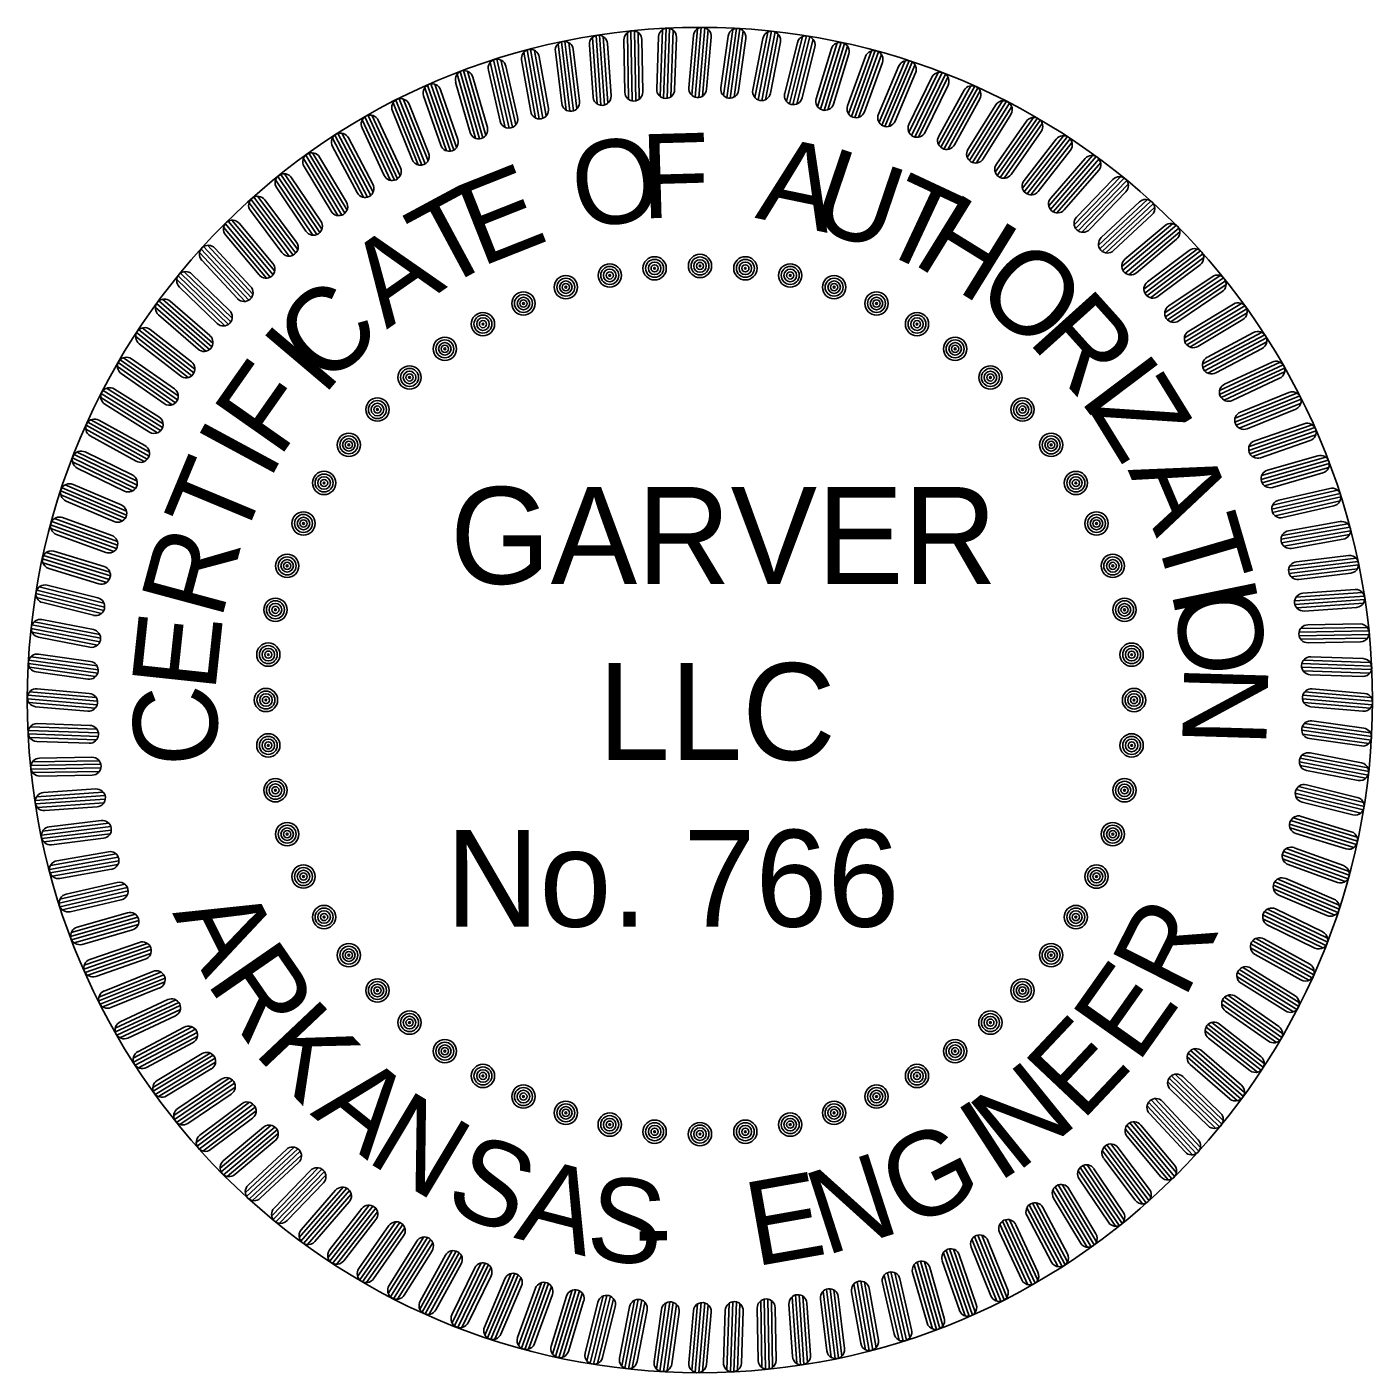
# Model space of a CAD drawing. Extents: x 0 to 19, y -0.6 to 11.2.
# Drawn here: x 17.822 to 19.023, y 2.492 to 3.693 of the extents above; entities that cross this region are included whole.
import ezdxf

# ---------------------------------------------------------------- set-up
doc = ezdxf.new("R2010")
doc.units = 0
for name, color, linetype in [('G-ANNO-STMP', 7, 'Continuous'), ('G-ANNO-TEXT', 7, 'Continuous'), ('G-No Plot-Stamp-1', 7, 'Continuous')]:
    doc.layers.add(name, color=color, linetype=linetype)

# ---------------------------------------------------------------- blocks, each defined once
blk = doc.blocks.new('SEALDO')
at = {"layer": 'G-ANNO-TEXT'}
for radius in [0.0396, 0.0305, 0.0213, 0.0122, 0.00305]:
    blk.add_circle((1.403, -0.4559), radius, dxfattribs=at)
blk = doc.blocks.new('SEALRI')
at = {"layer": 'G-ANNO-TEXT'}
for p, q in [((-0.0226, 2.2583), (-0.0381, 2.0809)), ((-0.0083, 2.2815), (-0.0281, 2.0555)), ((0.0043, 2.2859), (-0.0164, 2.049)), ((0.0164, 2.2848), (-0.0043, 2.0479)), ((0.0281, 2.2783), (0.0083, 2.0523)), ((0.0226, 2.0756), (0.0381, 2.253))]:
    blk.add_line(p, q, dxfattribs=at)
for centre, start, end in [((0.0078, 2.2556), 355, 175), ((-0.0078, 2.0782), 175, 355)]:
    blk.add_arc(centre, 0.0305, start, end, dxfattribs=at)

msp = doc.modelspace()

# ---------------------------------------------------------------- linework, layer by layer
at = {"layer": 'G-No Plot-Stamp-1'}
msp.add_circle((18.4222, 3.0925), 0.6, dxfattribs=at)

# ---------------------------------------------------------------- block references
at = {"layer": 'G-ANNO-STMP'}
for name, xscale, yscale, rotation in [('SEALRI', 0.2624620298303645, 0.2624620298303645, 9), ('SEALRI', 0.2624620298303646, 0.26246202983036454, 6), ('SEALRI', 0.2624620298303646, 0.2624620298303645, 3.0000000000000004), ('SEALRI', 0.26246202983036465, 0.2624620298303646, -2.9999999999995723), ('SEALRI', 0.2624620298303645, 0.2624620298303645, -5.9999999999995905), ('SEALRI', 0.2624620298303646, 0.26246202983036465, -8.999999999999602), ('SEALRI', 0.2624620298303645, 0.2624620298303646, 15.000000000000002), ('SEALRI', 0.2624620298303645, 0.2624620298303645, 12.000000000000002), ('SEALRI', 0.2624620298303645, 0.26246202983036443, -11.999999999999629), ('SEALRI', 0.2624620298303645, 0.2624620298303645, -14.999999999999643), ('SEALRI', 0.2624620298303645, 0.26246202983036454, 18), ('SEALRI', 0.26246202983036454, 0.2624620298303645, -17.99999999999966), ('SEALRI', 0.26246202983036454, 0.26246202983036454, 20.999999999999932), ('SEALRI', 0.2624620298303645, 0.26246202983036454, -20.999999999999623), ('SEALRI', 0.26246202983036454, 0.26246202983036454, 23.99999999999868), ('SEALRI', 0.2624620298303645, 0.26246202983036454, -23.999999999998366), ('SEALRI', 0.2624620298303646, 0.26246202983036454, 26.99999999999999), ('SEALRI', 0.26246202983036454, 0.26246202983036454, -26.999999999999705), ('SEALRI', 0.2624620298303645, 0.2624620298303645, 30.00000000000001), ('SEALRI', 0.26246202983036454, 0.2624620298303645, -29.99999999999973), ('SEALRI', 0.2624620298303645, 0.26246202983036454, 33), ('SEALRI', 0.26246202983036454, 0.2624620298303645, -32.999999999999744), ('SEALRI', 0.2624620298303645, 0.2624620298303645, 36), ('SEALRI', 0.2624620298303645, 0.2624620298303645, -35.999999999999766), ('SEALRI', 0.26246202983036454, 0.26246202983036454, 38.999999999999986), ('SEALRI', 0.26246202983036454, 0.2624620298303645, -38.999999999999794), ('SEALRI', 0.26246202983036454, 0.2624620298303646, 41.999999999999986), ('SEALRI', 0.26246202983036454, 0.2624620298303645, -41.99999999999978), ('SEALRI', 0.26246202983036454, 0.2624620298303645, 44.999999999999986), ('SEALRI', 0.26246202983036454, 0.2624620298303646, -44.999999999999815), ('SEALRI', 0.2624620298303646, 0.26246202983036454, 47.99999999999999), ('SEALRI', 0.26246202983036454, 0.2624620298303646, -47.99999999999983), ('SEALDO', 0.2624620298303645, 0.26246202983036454, 119.99999999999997), ('SEALDO', 0.2624620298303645, 0.26246202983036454, 113.99999999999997), ('SEALDO', 0.26246202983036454, 0.2624620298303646, 107.99999999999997), ('SEALDO', 0.26246202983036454, 0.26246202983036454, 101.99999999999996), ('SEALDO', 0.2624620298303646, 0.2624620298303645, 95.99999999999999), ('SEALRI', 0.26246202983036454, 0.26246202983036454, 50.99999999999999), ('SEALDO', 0.2624620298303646, 0.26246202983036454, 125.99999999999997), ('SEALDO', 0.26246202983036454, 0.26246202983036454, 90), ('SEALRI', 0.2624620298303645, 0.26246202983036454, -50.999999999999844), ('SEALDO', 0.2624620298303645, 0.26246202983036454, 131.99999999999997), ('SEALRI', 0.2624620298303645, 0.2624620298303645, 54), ('SEALDO', 0.2624620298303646, 0.26246202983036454, 83.99999999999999), ('SEALRI', 0.2624620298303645, 0.26246202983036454, -53.99999999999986), ('SEALDO', 0.26246202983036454, 0.26246202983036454, 138), ('SEALDO', 0.2624620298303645, 0.26246202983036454, 77.99999999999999), ('SEALRI', 0.26246202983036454, 0.2624620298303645, 56.99999999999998), ('SEALRI', 0.2624620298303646, 0.26246202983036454, -56.999999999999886), ('SEALDO', 0.2624620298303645, 0.26246202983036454, 144), ('SEALDO', 0.2624620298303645, 0.26246202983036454, 72), ('SEALRI', 0.2624620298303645, 0.2624620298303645, 59.999999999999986), ('SEALRI', 0.2624620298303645, 0.26246202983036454, -59.99999999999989), ('SEALDO', 0.26246202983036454, 0.2624620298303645, 150), ('SEALDO', 0.26246202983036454, 0.2624620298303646, 66.00000000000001), ('SEALRI', 0.26246202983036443, 0.2624620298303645, 63), ('SEALDO', 0.26246202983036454, 0.2624620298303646, 156.00000000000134), ('SEALDO', 0.26246202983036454, 0.2624620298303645, 60.00000000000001), ('SEALRI', 0.2624620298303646, 0.26246202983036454, -62.99999999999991), ('SEALRI', 0.26246202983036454, 0.2624620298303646, 65.99999999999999), ('SEALRI', 0.26246202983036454, 0.2624620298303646, -65.99999999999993), ('SEALDO', 0.2624620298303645, 0.26246202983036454, 162.00000000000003), ('SEALDO', 0.2624620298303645, 0.2624620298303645, 54), ('SEALRI', 0.26246202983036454, 0.2624620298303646, 68.99999999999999), ('SEALRI', 0.26246202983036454, 0.26246202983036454, -68.99999999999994), ('SEALDO', 0.26246202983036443, 0.2624620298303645, 168.00000000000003), ('SEALDO', 0.26246202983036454, 0.2624620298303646, 48.00000000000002), ('SEALRI', 0.2624620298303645, 0.26246202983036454, 72), ('SEALRI', 0.26246202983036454, 0.26246202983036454, -71.99999999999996), ('SEALRI', 0.2624620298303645, 0.26246202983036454, 75.00000000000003), ('SEALDO', 0.2624620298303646, 0.2624620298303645, 174.00000000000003), ('SEALDO', 0.2624620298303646, 0.26246202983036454, 42.000000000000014), ('SEALRI', 0.26246202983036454, 0.2624620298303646, -74.99999999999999), ('SEALRI', 0.2624620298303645, 0.2624620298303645, 78.00000000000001), ('SEALDO', 0.26246202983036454, 0.26246202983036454, -179.99999999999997), ('SEALDO', 0.2624620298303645, 0.2624620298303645, 36), ('SEALRI', 0.2624620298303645, 0.2624620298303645, -78), ('SEALRI', 0.2624620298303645, 0.2624620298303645, 81), ('SEALRI', 0.2624620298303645, 0.2624620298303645, -81.00000000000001), ('SEALDO', 0.26246202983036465, 0.26246202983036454, -173.99999999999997), ('SEALDO', 0.26246202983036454, 0.2624620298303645, 29.999999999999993), ('SEALRI', 0.2624620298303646, 0.26246202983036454, 84.00000000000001), ('SEALRI', 0.2624620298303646, 0.2624620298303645, -84.00000000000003), ('SEALDO', 0.26246202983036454, 0.26246202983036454, 23.99999999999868), ('SEALDO', 0.2624620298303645, 0.26246202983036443, -167.99999999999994), ('SEALRI', 0.26246202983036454, 0.26246202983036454, 87.00000000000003), ('SEALRI', 0.26246202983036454, 0.26246202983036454, -87.00000000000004), ('SEALRI', 0.26246202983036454, 0.26246202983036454, 90.00000000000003), ('SEALDO', 0.2624620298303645, 0.26246202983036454, -161.99999999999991), ('SEALDO', 0.2624620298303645, 0.26246202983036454, 18), ('SEALRI', 0.26246202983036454, 0.26246202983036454, -90.00000000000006), ('SEALRI', 0.2624620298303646, 0.2624620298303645, 93), ('SEALRI', 0.2624620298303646, 0.26246202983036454, -93.00000000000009), ('SEALDO', 0.2624620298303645, 0.26246202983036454, -156.00000000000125), ('SEALDO', 0.2624620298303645, 0.2624620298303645, 12.000000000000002), ('SEALRI', 0.2624620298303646, 0.26246202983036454, 96.00000000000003), ('SEALRI', 0.26246202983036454, 0.2624620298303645, -96.0000000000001), ('SEALDO', 0.26246202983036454, 0.26246202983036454, -149.99999999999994), ('SEALRI', 0.26246202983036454, 0.26246202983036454, 99.00000000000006), ('SEALDO', 0.2624620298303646, 0.26246202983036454, 6), ('SEALRI', 0.26246202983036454, 0.2624620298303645, -99.00000000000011), ('SEALRI', 0.2624620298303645, 0.2624620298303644, 102.00000000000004), ('SEALRI', 0.2624620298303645, 0.2624620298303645, -102.00000000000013), ('SEALDO', 0.2624620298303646, 0.26246202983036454, -143.99999999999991), ('SEALRI', 0.26246202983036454, 0.2624620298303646, 105.00000000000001), ('SEALRI', 0.26246202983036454, 0.2624620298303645, -105.00000000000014), ('SEALDO', 0.26246202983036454, 0.2624620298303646, -137.9999999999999), ('SEALDO', 0.26246202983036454, 0.2624620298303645, -6.000000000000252), ('SEALRI', 0.26246202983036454, 0.26246202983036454, 108.00000000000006), ('SEALRI', 0.26246202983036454, 0.2624620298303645, -108.00000000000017), ('SEALRI', 0.2624620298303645, 0.2624620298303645, 111.00000000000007), ('SEALDO', 0.26246202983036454, 0.26246202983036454, -131.99999999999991), ('SEALDO', 0.2624620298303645, 0.26246202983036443, -12.000000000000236), ('SEALRI', 0.26246202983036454, 0.26246202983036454, -111.00000000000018), ('SEALRI', 0.26246202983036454, 0.26246202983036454, 114.00000000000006), ('SEALRI', 0.26246202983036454, 0.2624620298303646, -114.0000000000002), ('SEALDO', 0.26246202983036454, 0.2624620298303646, -125.9999999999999), ('SEALDO', 0.2624620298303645, 0.26246202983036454, -18.000000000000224), ('SEALRI', 0.26246202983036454, 0.26246202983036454, 117.00000000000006), ('SEALDO', 0.2624620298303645, 0.26246202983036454, -119.99999999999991), ('SEALDO', 0.26246202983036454, 0.2624620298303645, -23.999999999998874), ('SEALRI', 0.26246202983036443, 0.2624620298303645, -117.00000000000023), ('SEALRI', 0.2624620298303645, 0.2624620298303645, 120.00000000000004), ('SEALRI', 0.26246202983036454, 0.2624620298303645, -120.00000000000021), ('SEALDO', 0.26246202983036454, 0.26246202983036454, -113.99999999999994), ('SEALDO', 0.2624620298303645, 0.26246202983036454, -30.00000000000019), ('SEALRI', 0.2624620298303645, 0.2624620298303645, 123.00000000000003), ('SEALRI', 0.2624620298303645, 0.26246202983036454, -123.00000000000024), ('SEALDO', 0.26246202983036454, 0.26246202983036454, -107.99999999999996), ('SEALDO', 0.2624620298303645, 0.2624620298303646, -36.00000000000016), ('SEALRI', 0.26246202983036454, 0.26246202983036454, 126.00000000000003), ('SEALRI', 0.26246202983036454, 0.2624620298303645, -126.00000000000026), ('SEALRI', 0.26246202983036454, 0.26246202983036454, 129.00000000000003), ('SEALDO', 0.2624620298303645, 0.26246202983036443, -101.99999999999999), ('SEALDO', 0.2624620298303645, 0.2624620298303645, -42.00000000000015), ('SEALRI', 0.2624620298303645, 0.26246202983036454, -129.00000000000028), ('SEALDO', 0.2624620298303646, 0.26246202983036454, -96), ('SEALDO', 0.26246202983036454, 0.26246202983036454, -48.00000000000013), ('SEALRI', 0.26246202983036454, 0.2624620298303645, 132), ('SEALDO', 0.26246202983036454, 0.26246202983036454, -54.000000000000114), ('SEALRI', 0.2624620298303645, 0.26246202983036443, -132.00000000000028), ('SEALDO', 0.26246202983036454, 0.26246202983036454, -90.00000000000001), ('SEALDO', 0.26246202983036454, 0.26246202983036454, -60.0000000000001), ('SEALRI', 0.2624620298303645, 0.26246202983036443, 135), ('SEALDO', 0.2624620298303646, 0.2624620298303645, -84.00000000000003), ('SEALDO', 0.26246202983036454, 0.26246202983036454, -78.00000000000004), ('SEALDO', 0.26246202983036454, 0.2624620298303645, -72.00000000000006), ('SEALDO', 0.2624620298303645, 0.26246202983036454, -66.00000000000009), ('SEALRI', 0.2624620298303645, 0.2624620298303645, -135.00000000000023), ('SEALRI', 0.26246202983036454, 0.26246202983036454, 138), ('SEALRI', 0.26246202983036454, 0.2624620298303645, -138.00000000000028), ('SEALRI', 0.2624620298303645, 0.26246202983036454, 140.99999999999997), ('SEALRI', 0.26246202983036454, 0.2624620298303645, -141.0000000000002), ('SEALRI', 0.2624620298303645, 0.26246202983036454, 144), ('SEALRI', 0.2624620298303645, 0.26246202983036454, -144.00000000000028), ('SEALRI', 0.2624620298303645, 0.26246202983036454, 146.99999999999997), ('SEALRI', 0.26246202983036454, 0.2624620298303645, -147.00000000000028), ('SEALRI', 0.2624620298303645, 0.26246202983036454, 149.99999999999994), ('SEALRI', 0.2624620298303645, 0.26246202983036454, -150.00000000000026), ('SEALRI', 0.2624620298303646, 0.26246202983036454, 152.99999999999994), ('SEALRI', 0.2624620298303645, 0.2624620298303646, -153.00000000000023), ('SEALRI', 0.2624620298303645, 0.2624620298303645, 156.00000000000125), ('SEALRI', 0.2624620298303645, 0.26246202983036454, 159), ('SEALRI', 0.26246202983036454, 0.26246202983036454, -159.00000000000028), ('SEALRI', 0.2624620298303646, 0.2624620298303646, -156.00000000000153), ('SEALRI', 0.2624620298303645, 0.2624620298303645, 161.99999999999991), ('SEALRI', 0.2624620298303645, 0.26246202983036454, -162.00000000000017), ('SEALRI', 0.2624620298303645, 0.26246202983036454, 164.99999999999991), ('SEALRI', 0.2624620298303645, 0.2624620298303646, -165.0000000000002), ('SEALRI', 0.2624620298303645, 0.26246202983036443, 167.99999999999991), ('SEALRI', 0.26246202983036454, 0.2624620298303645, 170.9999999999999), ('SEALRI', 0.26246202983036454, 0.2624620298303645, 173.9999999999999), ('SEALRI', 0.2624620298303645, 0.2624620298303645, -174.00000000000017), ('SEALRI', 0.26246202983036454, 0.2624620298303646, -171.00000000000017), ('SEALRI', 0.2624620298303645, 0.2624620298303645, -168.0000000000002), ('SEALRI', 0.2624620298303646, 0.2624620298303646, 176.9999999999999), ('SEALRI', 0.26246202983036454, 0.26246202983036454, 179.99999999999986), ('SEALRI', 0.2624620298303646, 0.26246202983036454, -177.00000000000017)]:
    msp.add_blockref(name, (18.4223, 3.0925), dxfattribs=dict(at, xscale=xscale, yscale=yscale, rotation=rotation))
at = {"layer": 'G-ANNO-STMP', "xscale": 0.26246202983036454, "yscale": 0.26246202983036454}
for name in ['SEALRI', 'SEALDO']:
    msp.add_blockref(name, (18.4223, 3.0925), dxfattribs=at)

# ---------------------------------------------------------------- texts
at = {"layer": 'G-ANNO-STMP'}
for s, rotation, p in [('O', 8.2771, (18.3136, 3.5123)), ('F', 1.6104, (18.3705, 3.522)), ('A', 348.2771, (18.4707, 3.5227)), ('U', 341.2772, (18.5176, 3.5152)), ('E', 21.6104, (18.2267, 3.4785)), ('T', 334.9438, (18.5765, 3.4962)), ('T', 28.2771, (18.1905, 3.4573)), ('H', 328.2771, (18.6103, 3.4828)), ('A', 34.9438, (18.1428, 3.4228)), ('O', 319.7874, (18.6645, 3.452)), ('C', 44.3881, (18.0896, 3.3699)), ('R', 311.9933, (18.7137, 3.4128)), ('I', 49.7408, (18.0858, 3.3622)), ('I', 307.0081, (18.7595, 3.3613)), ('F', 54.9438, (18.0468, 3.3073)), ('Z', 301.6104, (18.7683, 3.3523)), ('I', 61.6104, (18.0378, 3.2871)), ('T', 67.4314, (18.0126, 3.2289)), ('A', 292.9752, (18.8037, 3.2978)), ('T', 286.3085, (18.8272, 3.2435)), ('R', 74.9438, (17.9951, 3.1629)), ('I', 281.6104, (18.8422, 3.1908)), ('O', 276.4823, (18.8451, 3.1881)), ('E', 83.8985, (17.9897, 3.0987)), ('N', 268.2771, (18.8545, 3.1248)), ('C', 91.8842, (17.993, 3.0347)), ('A', 296.5747, (17.9514, 2.9025)), ('R', 63.0959, (18.8543, 2.8247)), ('R', 304.6183, (17.981, 2.8408)), ('E', 54.7309, (18.8126, 2.7672)), ('K', 313.3805, (18.0231, 2.778)), ('E', 46.6807, (18.7629, 2.7159)), ('A', 321.2584, (18.0738, 2.7232)), ('N', 38.9821, (18.705, 2.6701)), ('N', 329.1099, (18.1231, 2.6817)), ('I', 32.979, (18.6876, 2.6612)), ('G', 26.4132, (18.608, 2.6194)), ('S', 337.6294, (18.1923, 2.6396)), ('A', 345.4073, (18.2555, 2.613)), ('N', 17.8686, (18.5341, 2.5965)), ('S', 352.8046, (18.3191, 2.5952)), ('E', 10.0695, (18.4713, 2.5871)), ('-', 0.8385, (18.3644, 2.5854))]:
    msp.add_text(s, height=0.075, rotation=rotation, dxfattribs=at).set_placement(p)
for s, p in [('GARVER', (18.1993, 3.1961)), ('LLC', (18.3314, 3.039)), ('No. 766', (18.1956, 2.8903))]:
    msp.add_text(s, height=0.0864, dxfattribs=at).set_placement(p)

doc.saveas('drawing.dxf')
